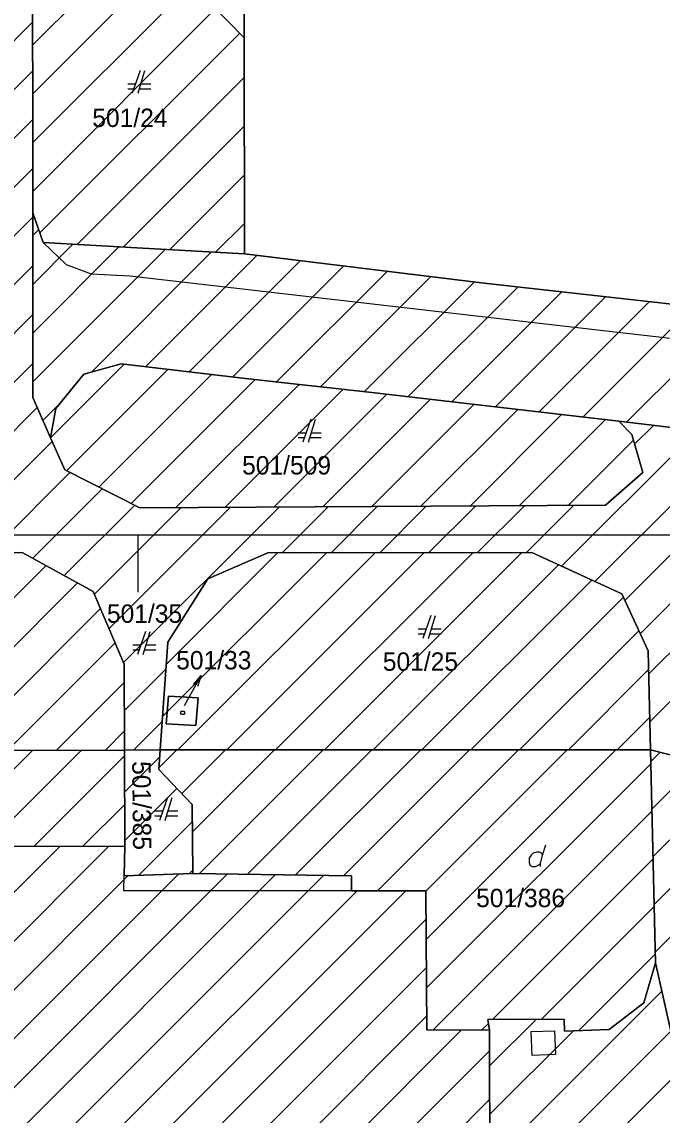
# Model space of a CAD drawing. Extents: x -264309 to -263505, y -1242443 to -1241763.
# Drawn here: x -264010.9 to -263955.2, y -1242101 to -1242005.9 of the extents above; entities that cross this region are included whole.
import ezdxf

# ---------------------------------------------------------------- set-up
doc = ezdxf.new("R2010")
doc.units = 0
for name, color, linetype in [('KN_2019_08_16_KLADPAR', 7, 'Continuous'), ('KN_2019_08_16_ZAPPAR', 7, 'Continuous'), ('RAM_NA_TLAC_10xA4_1-500', 7, 'Continuous'), ('SRAFY_PARCELY', 7, 'Continuous')]:
    doc.layers.add(name, color=color, linetype=linetype)

msp = doc.modelspace()

# ---------------------------------------------------------------- linework, layer by layer
at = {"layer": 'KN_2019_08_16_KLADPAR'}
for p, q in [((-263991.58, -1242007.28), (-263991.6, -1241998.65)), ((-263991.54, -1242026.1), (-263991.58, -1242007.28)), ((-264000.61, -1242010.12), (-264001.31, -1242012.12)), ((-264000.81, -1242012.12), (-264000.21, -1242010.12)), ((-264001.03, -1242011.32), (-264001.71, -1242011.32)), ((-264001.71, -1242011.72), (-264001.17, -1242011.72)), ((-264000.69, -1242011.72), (-263999.71, -1242011.72)), ((-263999.71, -1242011.32), (-264000.57, -1242011.32)), ((-263970.71, -1242028.65), (-263991.54, -1242026.1)), ((-263951.74, -1242030.76), (-263970.71, -1242028.65)), ((-263985.77, -1242040.48), (-263986.47, -1242042.48)), ((-263985.97, -1242042.48), (-263985.37, -1242040.48)), ((-263986.19, -1242041.68), (-263986.87, -1242041.68)), ((-263986.87, -1242042.08), (-263986.33, -1242042.08)), ((-263985.85, -1242042.08), (-263984.87, -1242042.08)), ((-263984.87, -1242041.68), (-263985.73, -1242041.68)), ((-263975.34, -1242057.55), (-263976.04, -1242059.55)), ((-263975.54, -1242059.55), (-263974.94, -1242057.55)), ((-264000.158, -1242058.939), (-264000.858, -1242060.939)), ((-264000.358, -1242060.939), (-263999.758, -1242058.939)), ((-263975.76, -1242058.75), (-263976.44, -1242058.75)), ((-263976.44, -1242059.15), (-263975.9, -1242059.15)), ((-263975.42, -1242059.15), (-263974.44, -1242059.15)), ((-263974.44, -1242058.75), (-263975.3, -1242058.75)), ((-264000.578, -1242060.139), (-264001.258, -1242060.139)), ((-263999.258, -1242060.139), (-264000.118, -1242060.139)), ((-264001.258, -1242060.539), (-264000.718, -1242060.539)), ((-264000.238, -1242060.539), (-263999.258, -1242060.539)), ((-263995.983, -1242063.551), (-263995.326, -1242062.77)), ((-263998.88, -1242069.26), (-263998.88, -1242069.26)), ((-263998.25, -1242073.39), (-263998.95, -1242075.39)), ((-263998.45, -1242075.39), (-263997.85, -1242073.39)), ((-263998.67, -1242074.59), (-263999.35, -1242074.59)), ((-263997.35, -1242074.59), (-263998.21, -1242074.59)), ((-263999.35, -1242074.99), (-263998.81, -1242074.99)), ((-263998.33, -1242074.99), (-263997.35, -1242074.99)), ((-263965.62, -1242078.42), (-263965.35, -1242077.52))]:
    msp.add_line(p, q, dxfattribs=at)
for points in [[(-263991.54, -1242026.1), (-264000.91, -1242025.57), (-264009.05, -1242025.11), (-264009.97, -1242022.53), (-264009.98, -1241996.19), (-264007.47, -1241993.39), (-264004.45, -1241994.11), (-263991.58, -1242007.28)], [(-264008.41, -1242042.11), (-264007.97, -1242039.55), (-264005.52, -1242036.55), (-264002.29, -1242035.66), (-263991.47, -1242036.94), (-263980.47, -1242038.14), (-263958.98, -1242040.66), (-263957.87, -1242041.8), (-263956.89, -1242045.13), (-263960.16, -1242047.97), (-264000.65, -1242048.19), (-264007.19, -1242044.89)], [(-264002.01, -1242061.78), (-264001.98, -1242069.27), (-264073, -1242069.31), (-264073.01, -1242062.91), (-264069.66, -1242054.98), (-264062.83, -1242052.18), (-264010.89, -1242052.07), (-264004.7, -1242055.47)], [(-263998.88, -1242069.26), (-263998.21, -1242059.87), (-263994.74, -1242054.37), (-263989.51, -1242052.11), (-263966.57, -1242052.07), (-263958.74, -1242055.68), (-263956.44, -1242060.64), (-263956.24, -1242069.24)], [(-263998.36, -1242066.98), (-263995.79, -1242067.14), (-263995.59, -1242064.72), (-263998.17, -1242064.57)], [(-263998.17, -1242064.57), (-263995.59, -1242064.72), (-263995.79, -1242067.14), (-263998.36, -1242066.98)], [(-263996.84, -1242065.87), (-263996.75, -1242066.02), (-263996.84, -1242066.17), (-263997.02, -1242066.17), (-263997.11, -1242066.02), (-263997.02, -1242065.87)], [(-264073, -1242069.31), (-264001.98, -1242069.27), (-264001.95, -1242077.64), (-264061.28, -1242077.73), (-264063.06, -1242079.88), (-264063.05, -1242082.02), (-264065.29, -1242082.03), (-264070.77, -1242081.01), (-264072.99, -1242076.85)], [(-264001.98, -1242069.27), (-263998.88, -1242069.26), (-263999, -1242070.95), (-263996.11, -1242074), (-263996.04, -1242080), (-264002.01, -1242080.21), (-264001.95, -1242077.64)], [(-263956.24, -1242069.24), (-263955.8, -1242087.79), (-263956.8, -1242091.26), (-263959.83, -1242093.59), (-263963.72, -1242093.73), (-263963.73, -1242092.7), (-263970.38, -1242092.72), (-263970.24, -1242093.63), (-263975.68, -1242093.61), (-263975.78, -1242081.51), (-263982.23, -1242081.51), (-263982.23, -1242080.21), (-263996.04, -1242080), (-263996.11, -1242074), (-263999, -1242070.95), (-263998.88, -1242069.26)], [(-263945.92, -1242287.35), (-263949.74, -1242287.63), (-263949.41, -1242196.68), (-263949.38, -1242187.85), (-263949.49, -1242175.05), (-263949.55, -1242159.39), (-263950.14, -1242129.96), (-263950.48, -1242111.43), (-263955.8, -1242087.79), (-263956.24, -1242069.24), (-263949.96, -1242070.83), (-263947.13, -1242072.33), (-263942.68, -1242071.91), (-263941.47, -1242124.08), (-263944.59, -1242125.87), (-263946.11, -1242129.79), (-263945.51, -1242159.3), (-263945.41, -1242187.87)]]:
    msp.add_lwpolyline(points, close=True, dxfattribs=at)
for points in [[(-263991.6, -1241998.65), (-263991.58, -1242007.28), (-264004.45, -1241994.11)], [(-264009.98, -1241996.19), (-264009.97, -1242022.53), (-264009.97, -1242038.58), (-264008.41, -1242042.11), (-264007.19, -1242044.89), (-264000.65, -1242048.19), (-263960.16, -1242047.97), (-263956.89, -1242045.13), (-263957.87, -1242041.8), (-263958.98, -1242040.66), (-263951.52, -1242041.54)], [(-263951.52, -1242041.54), (-263958.98, -1242040.66), (-263980.47, -1242038.14), (-263991.47, -1242036.94), (-264002.29, -1242035.66), (-264005.52, -1242036.55), (-264007.97, -1242039.55), (-264008.41, -1242042.11), (-264009.97, -1242038.58), (-264009.97, -1242022.53), (-264009.05, -1242025.11), (-264000.91, -1242025.57), (-263991.54, -1242026.1), (-263970.71, -1242028.65), (-263951.74, -1242030.76)], [(-263949.96, -1242070.83), (-263956.24, -1242069.24), (-263956.44, -1242060.64), (-263958.74, -1242055.68), (-263966.57, -1242052.07), (-263989.51, -1242052.11), (-263994.74, -1242054.37), (-263998.21, -1242059.87), (-263998.88, -1242069.26), (-264001.98, -1242069.27), (-264002.01, -1242061.78), (-264004.7, -1242055.47), (-264010.89, -1242052.07), (-264062.83, -1242052.18), (-264069.66, -1242054.98), (-264073.01, -1242062.91), (-264073, -1242069.31), (-264076.82, -1242069.31)], [(-263996.77, -1242065.4), (-263995.326, -1242062.77), (-263995.632, -1242063.743)], [(-264072.96, -1242101.25), (-264072.11, -1242100.28), (-264072.96, -1242099.3), (-264072.96, -1242094.5), (-264070.93, -1242094.55), (-264070.53, -1242091.66), (-264068.16, -1242088.59), (-264065.59, -1242088.27), (-264063.02, -1242088.27), (-264063.05, -1242082.02), (-264063.06, -1242079.88), (-264061.28, -1242077.73), (-264001.95, -1242077.64), (-264002.01, -1242080.21), (-263996.04, -1242080), (-263982.23, -1242080.21), (-263982.23, -1242081.51), (-263975.78, -1242081.51), (-263975.68, -1242093.61), (-263970.24, -1242093.63), (-263970.22, -1242106.22)], [(-263965.8, -1242079.41), (-263965.8, -1242079.14), (-263965.62, -1242078.42), (-263965.71, -1242078.24), (-263965.89, -1242078.15), (-263966.16, -1242078.15), (-263966.43, -1242078.24), (-263966.61, -1242078.42), (-263966.79, -1242078.69), (-263966.79, -1242079.05), (-263966.7, -1242079.32), (-263966.52, -1242079.41), (-263966.25, -1242079.41), (-263966.07, -1242079.32), (-263965.8, -1242079.14)], [(-263970.22, -1242106.22), (-263970.24, -1242093.63), (-263970.38, -1242092.72), (-263963.73, -1242092.7), (-263963.72, -1242093.73), (-263959.83, -1242093.59), (-263956.8, -1242091.26), (-263955.8, -1242087.79), (-263950.48, -1242111.43)]]:
    msp.add_lwpolyline(points, dxfattribs=at)
at = {"layer": 'KN_2019_08_16_ZAPPAR'}
for p, q in [((-264002.04, -1242081.51), (-264002.01, -1242080.21)), ((-263982.23, -1242081.51), (-264002.04, -1242081.51)), ((-263964.5, -1242095.76), (-263966.54, -1242095.84))]:
    msp.add_line(p, q, dxfattribs=at)
for points in [[(-264009.05, -1242025.11), (-264007.06, -1242027.03), (-264004.88, -1242027.82), (-264001.52, -1242027.99), (-263958.32, -1242033), (-263951.68, -1242033.75), (-263943.48, -1242034.79), (-263940.72, -1242035.02), (-263926.91, -1242036.98), (-263897.04, -1242039.59), (-263857.13, -1242042.91), (-263837.1, -1242044.85)], [(-263966.54, -1242095.84), (-263966.62, -1242093.77), (-263964.58, -1242093.69), (-263964.5, -1242095.76)]]:
    msp.add_lwpolyline(points, dxfattribs=at)
at = {"layer": 'RAM_NA_TLAC_10xA4_1-500'}
msp.add_line((-264000.825, -1242050.537), (-264000.825, -1242055.537), dxfattribs=at)
msp.add_lwpolyline([(-264210.825, -1242050.537), (-264105.825, -1242050.537), (-264000.825, -1242050.537), (-263895.825, -1242050.537), (-263790.825, -1242050.537), (-263685.825, -1242050.537), (-263685.825, -1242199.037), (-263685.825, -1242347.537), (-263790.825, -1242347.537), (-263895.825, -1242347.537), (-264000.825, -1242347.537), (-264105.825, -1242347.537), (-264210.825, -1242347.537), (-264210.825, -1242199.037)], close=True, dxfattribs=at)
at = {"layer": 'SRAFY_PARCELY'}
for p, q in [((-264009.976, -1242007.927), (-264000.352, -1241998.304)), ((-264009.974, -1242012.168), (-263998.255, -1242000.449)), ((-264009.972, -1242016.409), (-263996.158, -1242002.595)), ((-264009.971, -1242020.65), (-263994.061, -1242004.741)), ((-264014.033, -1242009.986), (-264009.976, -1242005.929)), ((-264009.349, -1242024.271), (-263991.964, -1242006.887)), ((-264014.025, -1242014.22), (-264009.975, -1242010.17)), ((-264006.111, -1242025.276), (-263991.573, -1242010.738)), ((-264014.017, -1242018.455), (-264009.973, -1242014.411)), ((-264002.095, -1242025.503), (-263991.564, -1242014.971)), ((-264014.009, -1242022.69), (-264009.971, -1242018.652)), ((-263998.08, -1242025.73), (-263991.555, -1242019.205)), ((-264014.001, -1242026.924), (-264009.97, -1242022.893)), ((-264009.97, -1242024.501), (-264009.452, -1242023.983)), ((-263994.064, -1242025.957), (-263991.546, -1242023.439)), ((-264009.97, -1242028.744), (-264006.482, -1242025.255)), ((-264009.97, -1242032.986), (-264002.466, -1242025.482)), ((-264009.97, -1242037.229), (-263998.45, -1242025.709)), ((-264004.869, -1242036.371), (-263994.435, -1242025.936)), ((-264000.167, -1242035.911), (-263990.485, -1242026.229)), ((-263996.373, -1242036.36), (-263986.705, -1242026.692)), ((-264013.993, -1242031.159), (-264009.97, -1242027.136)), ((-263992.579, -1242036.809), (-263982.925, -1242027.155)), ((-263988.763, -1242037.235), (-263979.145, -1242027.617)), ((-263984.938, -1242037.653), (-263975.365, -1242028.08)), ((-263981.113, -1242038.07), (-263971.585, -1242028.543)), ((-263977.311, -1242038.51), (-263967.776, -1242028.976)), ((-263973.513, -1242038.956), (-263963.958, -1242029.401)), ((-263969.716, -1242039.401), (-263960.14, -1242029.826)), ((-263965.918, -1242039.846), (-263956.322, -1242030.25)), ((-263962.121, -1242040.292), (-263952.504, -1242030.675)), ((-264013.985, -1242035.394), (-264009.97, -1242031.378)), ((-263958.324, -1242040.737), (-263948.712, -1242031.125)), ((-264015.332, -1242040.983), (-264009.97, -1242035.621)), ((-264008.405, -1242042.079), (-264002.018, -1242035.692)), ((-264007.046, -1242044.963), (-263998.224, -1242036.141)), ((-264004.226, -1242046.385), (-263994.431, -1242036.59)), ((-264001.406, -1242047.808), (-263990.63, -1242037.032)), ((-263997.529, -1242048.173), (-263986.804, -1242037.449)), ((-263993.263, -1242048.15), (-263982.979, -1242037.866)), ((-263988.997, -1242048.127), (-263979.163, -1242038.293)), ((-264022.2, -1242052.094), (-264009.577, -1242039.47)), ((-264009.084, -1242040.585), (-264007.62, -1242039.122)), ((-263984.731, -1242048.104), (-263975.366, -1242038.739)), ((-263980.465, -1242048.08), (-263971.569, -1242039.184)), ((-263976.199, -1242048.057), (-263967.771, -1242039.629)), ((-263971.934, -1242048.034), (-263963.974, -1242040.074)), ((-263967.668, -1242048.011), (-263960.177, -1242040.52)), ((-263957.616, -1242042.664), (-263955.967, -1242041.015)), ((-263963.976, -1242053.266), (-263952.172, -1242041.463)), ((-263963.402, -1242047.988), (-263957.721, -1242042.307)), ((-264017.949, -1242052.085), (-264008.277, -1242042.413)), ((-264013.697, -1242052.076), (-264006.739, -1242045.118)), ((-263961.072, -1242054.605), (-263951.451, -1242044.984)), ((-264009.96, -1242052.581), (-264003.919, -1242046.541)), ((-264007.221, -1242054.085), (-264001.099, -1242047.963)), ((-263975.523, -1242052.086), (-263971.469, -1242048.031)), ((-263971.273, -1242052.078), (-263967.203, -1242048.008)), ((-263967.023, -1242052.071), (-263962.937, -1242047.985)), ((-264004.599, -1242055.706), (-263997.064, -1242048.171)), ((-264003.331, -1242058.681), (-263992.798, -1242048.147)), ((-264002.063, -1242061.655), (-263988.532, -1242048.124)), ((-263988.273, -1242052.108), (-263984.266, -1242048.101)), ((-263984.023, -1242052.1), (-263980, -1242048.078)), ((-263979.773, -1242052.093), (-263975.735, -1242048.055)), ((-263958.475, -1242056.251), (-263951.367, -1242049.143)), ((-263998.673, -1242066.355), (-263984.419, -1242052.101)), ((-263998.347, -1242061.786), (-263988.669, -1242052.109)), ((-263997.334, -1242069.259), (-263980.169, -1242052.094)), ((-263993.09, -1242069.257), (-263975.919, -1242052.086)), ((-263988.845, -1242069.255), (-263971.669, -1242052.079)), ((-263984.6, -1242069.253), (-263967.419, -1242052.071)), ((-264024.877, -1242069.283), (-264008.808, -1242053.214)), ((-263980.356, -1242069.251), (-263964.246, -1242053.142)), ((-263957.131, -1242059.15), (-263951.284, -1242053.302)), ((-263976.111, -1242069.249), (-263961.342, -1242054.48)), ((-264020.632, -1242069.281), (-264006.069, -1242054.718)), ((-263971.866, -1242069.247), (-263958.6, -1242055.981)), ((-264016.387, -1242069.278), (-264004.066, -1242056.957)), ((-263956.393, -1242062.654), (-263951.2, -1242057.461)), ((-263967.622, -1242069.245), (-263957.256, -1242058.88)), ((-264012.142, -1242069.276), (-264002.798, -1242059.932)), ((-264001.994, -1242065.829), (-263998.377, -1242062.212)), ((-263963.377, -1242069.243), (-263956.402, -1242062.268)), ((-263956.297, -1242066.8), (-263951.116, -1242061.62)), ((-264007.897, -1242069.273), (-264002.004, -1242063.38)), ((-264001.19, -1242069.267), (-263998.703, -1242066.78)), ((-263959.133, -1242069.241), (-263956.306, -1242066.414)), ((-264003.652, -1242069.271), (-264001.987, -1242067.606)), ((-264018.36, -1242077.665), (-264009.969, -1242069.274)), ((-264014.111, -1242077.658), (-264005.724, -1242069.272)), ((-264009.862, -1242077.652), (-264001.978, -1242069.769)), ((-264001.967, -1242072.904), (-263998.923, -1242069.86)), ((-263998.99, -1242070.808), (-263997.442, -1242069.259)), ((-263997, -1242073.061), (-263993.197, -1242069.257)), ((-263996.082, -1242076.385), (-263988.952, -1242069.255)), ((-263995.463, -1242080.009), (-263984.708, -1242069.253)), ((-263991.284, -1242080.072), (-263980.463, -1242069.251)), ((-263987.105, -1242080.136), (-263976.218, -1242069.249)), ((-263982.926, -1242080.199), (-263971.974, -1242069.247)), ((-263979.994, -1242081.51), (-263967.729, -1242069.245)), ((-263975.78, -1242081.539), (-263963.485, -1242069.243)), ((-263975.745, -1242085.746), (-263959.24, -1242069.241)), ((-263956.216, -1242070.265), (-263955.403, -1242069.452)), ((-263975.71, -1242089.954), (-263956.211, -1242070.455)), ((-263956.117, -1242074.41), (-263952.017, -1242070.309)), ((-263956.019, -1242078.554), (-263948.872, -1242071.407)), ((-264001.952, -1242077.132), (-263997.429, -1242072.608)), ((-263955.921, -1242082.698), (-263945.388, -1242072.166)), ((-263955.822, -1242086.843), (-263942.639, -1242073.659)), ((-264005.613, -1242077.646), (-264001.963, -1242073.996)), ((-263975.125, -1242093.612), (-263956.113, -1242074.6)), ((-264000.743, -1242080.165), (-263996.092, -1242075.515)), ((-264052.446, -1242122.496), (-264007.599, -1242077.649)), ((-264048.202, -1242122.494), (-264003.35, -1242077.642)), ((-263969.989, -1242092.719), (-263956.015, -1242078.744)), ((-264043.957, -1242122.492), (-264001.663, -1242080.198)), ((-264039.713, -1242122.49), (-263997.265, -1242080.043)), ((-264035.468, -1242122.489), (-263993.026, -1242080.046)), ((-264031.224, -1242122.487), (-263988.846, -1242080.109)), ((-264026.979, -1242122.485), (-263984.667, -1242080.173)), ((-263996.346, -1242080.011), (-263996.043, -1242079.709)), ((-264022.735, -1242122.483), (-263981.762, -1242081.51)), ((-264018.49, -1242122.481), (-263977.519, -1242081.51)), ((-263965.734, -1242092.706), (-263955.916, -1242082.888)), ((-264016.478, -1242124.712), (-263975.759, -1242083.993)), ((-263962.47, -1242093.685), (-263955.818, -1242087.033)), ((-264016.475, -1242128.951), (-263975.725, -1242088.201)), ((-263970.222, -1242105.229), (-263955.246, -1242090.253)), ((-264016.472, -1242133.191), (-263975.69, -1242092.409)), ((-263970.235, -1242096.757), (-263966.185, -1242092.707)), ((-264016.441, -1242137.403), (-263972.66, -1242093.621)), ((-263970.898, -1242093.628), (-263970.328, -1242093.057)), ((-263970.228, -1242100.993), (-263962.937, -1242093.702)), ((-263975.598, -1242114.848), (-263954.466, -1242093.716)), ((-264027.478, -1242152.682), (-263970.237, -1242095.441)), ((-263962.726, -1242106.219), (-263953.687, -1242097.18)), ((-264027.444, -1242156.891), (-263970.23, -1242099.677))]:
    msp.add_line(p, q, dxfattribs=at)

# ---------------------------------------------------------------- texts
at = {"layer": 'KN_2019_08_16_KLADPAR'}
for s, p in [('501/24', (-264004.789, -1242015.05)), ('501/509', (-263991.756, -1242045.29)), ('501/35', (-264003.517, -1242058.198)), ('501/33', (-263997.493, -1242062.25)), ('501/25', (-263979.519, -1242062.37)), ('501/386', (-263971.401, -1242082.94))]:
    msp.add_text(s, height=1.6, dxfattribs=at).set_placement(p)
msp.add_text('501/385', height=1.6, rotation=270.60797, dxfattribs=at).set_placement((-264001.322, -1242070.237))

doc.saveas('drawing.dxf')
